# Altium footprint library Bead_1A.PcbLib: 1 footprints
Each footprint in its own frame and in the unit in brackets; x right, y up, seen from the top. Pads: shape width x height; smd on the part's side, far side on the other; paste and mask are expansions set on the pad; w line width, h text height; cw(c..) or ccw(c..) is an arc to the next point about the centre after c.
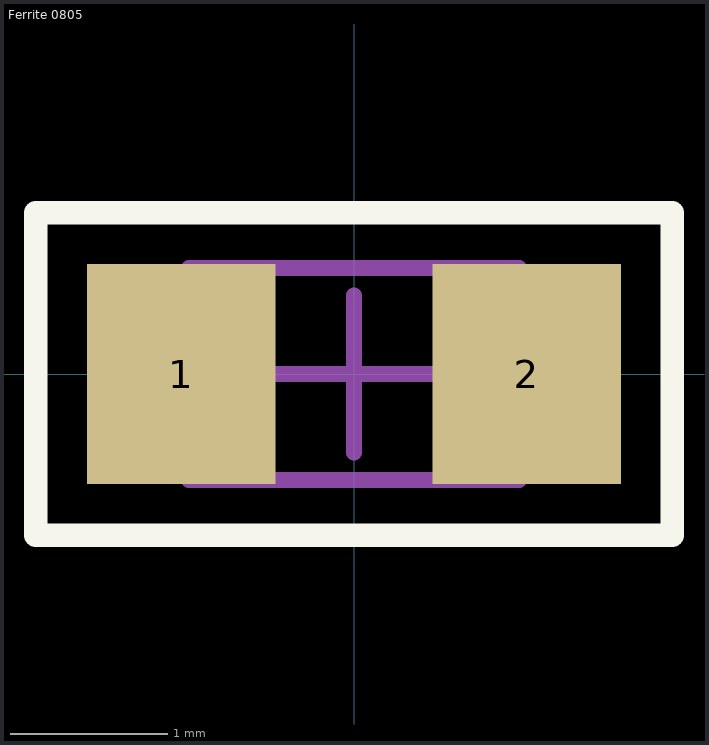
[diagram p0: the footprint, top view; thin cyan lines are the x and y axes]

## Ferrite 0805 [mm]
pads (2):
  rect 1.2x1.4 smd: 1(-1.1,0) 2(1.1,0)
Top Overlay:
  lines w0.15: -2.025,-1.025 2.025,-1.025 2.025,1.025 -2.025,1.025 -2.025,-1.025
Mechanical 13:
  lines w0.1: -1.05,-0.675 1.05,-0.675 1.05,0.675 -1.05,0.675 -1.05,-0.675
Mechanical 15:
  lines w0.1: -0.5,0 0.5,0 ; 0,-0.5 0,0.5
3D body "Ferrite 0805.step": height 0.8, standoff 0, extent -1.279,-0.62 1.229,0.625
